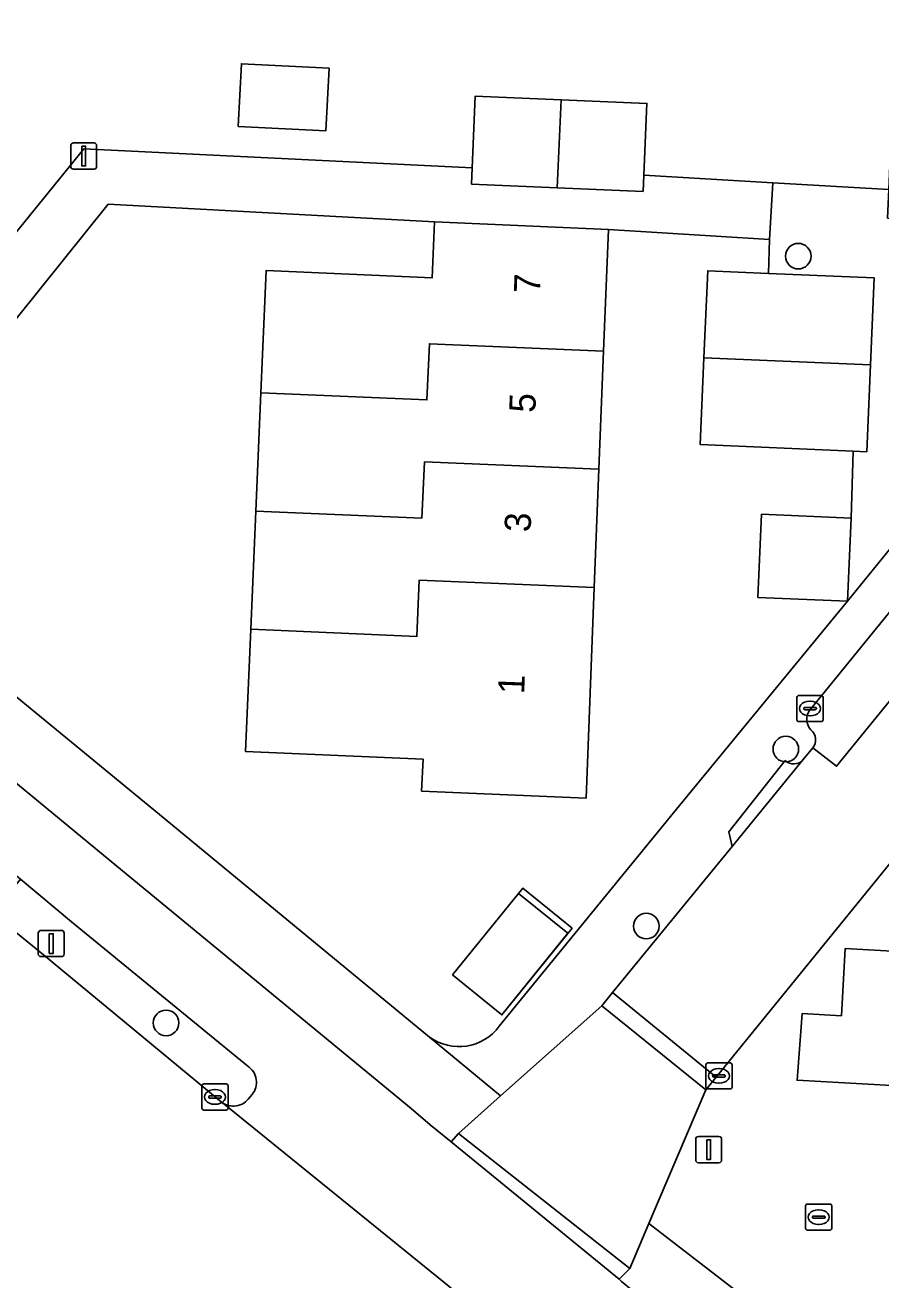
# Model space of a CAD drawing. Extents: x 162989 to 165008, y 383432 to 384338.
# Drawn here: x 164414.28 to 164447, y 383543.79 to 383591.76 of the extents above; entities that cross this region are included whole.
import ezdxf

# ---------------------------------------------------------------- set-up
doc = ezdxf.new("R2010")
doc.units = 0
for name, color, linetype in [('IMGEO_Boom', 7, 'Continuous'), ('IMGEO_Erf', 7, 'Continuous'), ('IMGEO_Fietspad_open', 7, 'Continuous'), ('IMGEO_Groenvoorziening', 7, 'Continuous'), ('IMGEO_Kolk', 7, 'Continuous'), ('IMGEO_Lichtmast', 7, 'Continuous'), ('IMGEO_Pand', 7, 'Continuous'), ('IMGEO_Pand_nummerreeks', 7, 'Continuous'), ('IMGEO_Pand_vergunning_verleend', 7, 'Continuous'), ('IMGEO_Parkeervlak_open', 7, 'Continuous'), ('IMGEO_Rijbaan_lokaal_open', 7, 'Continuous'), ('IMGEO_Voetpad_open', 7, 'Continuous')]:
    doc.layers.add(name, color=color, linetype=linetype)

msp = doc.modelspace()

# ---------------------------------------------------------------- linework, layer by layer
at = {"layer": 'IMGEO_Boom'}
for centre in [(164443.845, 383582.925), (164443.368, 383564.084), (164438.034, 383557.317), (164419.671, 383553.617)]:
    msp.add_circle(centre, 0.489, dxfattribs=at)
at = {"layer": 'IMGEO_Erf'}
for points in [[(164405.306, 383573.211), (164416.525, 383587.022), (164431.377, 383586.306), (164431.495, 383589.046), (164434.775, 383588.905), (164438.055, 383588.764), (164437.937, 383586.015), (164442.875, 383585.731), (164447.306, 383585.477), (164447.527, 383590.599), (164450.828, 383590.457), (164454.13, 383590.315), (164453.951, 383586.161), (164454.949, 383586.096), (164455.073, 383588.585), (164460.646, 383588.116), (164466.476, 383595.416), (164468.237, 383598.107)], [(164432.411, 383553.488), (164439.299, 383561.922), (164445.728, 383569.733), (164442.304, 383569.88), (164442.441, 383573.061), (164445.865, 383572.914), (164445.941, 383575.47), (164440.096, 383575.721), (164440.239, 383579.042), (164440.382, 383582.365), (164442.702, 383582.265), (164442.744, 383583.566), (164436.586, 383583.949), (164436.402, 383579.296), (164436.224, 383574.777), (164436.046, 383570.258), (164435.728, 383562.21), (164429.442, 383562.48), (164429.495, 383563.702), (164422.707, 383563.993), (164422.908, 383568.663), (164423.102, 383573.182), (164423.296, 383577.701), (164423.497, 383582.372), (164429.846, 383582.099), (164429.938, 383584.235), (164417.457, 383584.908), (164406.935, 383571.831), (164419.421, 383561.588), (164429.74, 383553.077)]]:
    msp.add_lwpolyline(points, dxfattribs=at)
for points in [[(164425.903, 383590.114), (164425.784, 383587.716), (164422.429, 383587.883), (164422.548, 383590.281)], [(164430.622, 383555.452), (164433.307, 383558.765), (164435.196, 383557.234), (164432.511, 383553.921)]]:
    msp.add_lwpolyline(points, close=True, dxfattribs=at)
msp.add_arc((164430.869, 383554.627), 1.918, 233.9466, 323.5489, dxfattribs=at)
at = {"layer": 'IMGEO_Fietspad_open'}
for points in [[(164320.149, 383636.549), (164338.569, 383621.368), (164355.855, 383607.134), (164360.495, 383603.371), (164385.072, 383583.018), (164402.919, 383568.352), (164414.101, 383559.114), (164416.06, 383557.479), (164422.791, 383551.963)], [(164438.67, 383542.429), (164437.09, 383543.73), (164436.992, 383543.815), (164430.566, 383549.073), (164429.773, 383549.72), (164429.037, 383550.342), (164417.789, 383559.607), (164405.287, 383569.915), (164386.954, 383585.032), (164362.228, 383605.446)], [(164421.813, 383550.569), (164441.129, 383534.933)], [(164422.959, 383550.88), (164422.815, 383550.707)]]:
    msp.add_lwpolyline(points, dxfattribs=at)
for centre, radius, start, end in [((164422.402, 383551.348), 0.727, 319.9447, 57.6907), ((164422.237, 383551.182), 0.745, 235.3669, 273.0368), ((164422.24, 383551.186), 0.748, 272.7924, 320.2526)]:
    msp.add_arc(centre, radius, start, end, dxfattribs=at)
at = {"layer": 'IMGEO_Groenvoorziening'}
for points in [[(164416.06, 383557.479), (164414.101, 383559.114), (164413.026, 383557.813), (164414.983, 383556.218), (164421.541, 383550.787), (164421.715, 383550.649), (164421.813, 383550.569)], [(164422.791, 383551.963), (164416.06, 383557.479)], [(164422.815, 383550.707), (164422.959, 383550.88)]]:
    msp.add_lwpolyline(points, dxfattribs=at)
for centre, radius, start, end in [((164422.402, 383551.348), 0.727, 319.9447, 57.6907), ((164422.237, 383551.182), 0.745, 235.3669, 273.0368), ((164422.24, 383551.186), 0.748, 272.7924, 320.2526)]:
    msp.add_arc(centre, radius, start, end, dxfattribs=at)
at = {"layer": 'IMGEO_Kolk'}
for p, q in [((164443.794, 383565.207), (164443.794, 383566.059)), ((164443.869, 383566.133), (164444.721, 383566.133)), ((164444.282, 383565.913), (164444.307, 383565.913)), ((164444.795, 383566.059), (164444.795, 383565.207)), ((164444.053, 383565.627), (164444.053, 383565.639)), ((164444.491, 383565.59), (164444.093, 383565.59)), ((164444.096, 383565.676), (164444.494, 383565.676)), ((164444.537, 383565.639), (164444.537, 383565.627)), ((164444.721, 383565.133), (164443.869, 383565.133)), ((164444.305, 383565.353), (164444.28, 383565.353)), ((164440.311, 383551.165), (164440.311, 383552.017)), ((164440.386, 383552.091), (164441.238, 383552.091)), ((164441.312, 383552.017), (164441.312, 383551.165)), ((164440.57, 383551.585), (164440.57, 383551.597)), ((164441.008, 383551.548), (164440.61, 383551.548)), ((164440.613, 383551.634), (164441.011, 383551.634)), ((164440.799, 383551.871), (164440.824, 383551.871)), ((164441.054, 383551.597), (164441.054, 383551.585)), ((164421.04, 383550.36), (164421.04, 383551.212)), ((164421.115, 383551.286), (164421.967, 383551.286)), ((164421.528, 383551.066), (164421.553, 383551.066)), ((164422.041, 383551.212), (164422.041, 383550.36)), ((164441.238, 383551.091), (164440.386, 383551.091)), ((164440.822, 383551.311), (164440.797, 383551.311)), ((164421.299, 383550.78), (164421.299, 383550.792)), ((164421.737, 383550.743), (164421.339, 383550.743)), ((164421.342, 383550.829), (164421.74, 383550.829)), ((164421.783, 383550.792), (164421.783, 383550.78)), ((164421.967, 383550.286), (164421.115, 383550.286)), ((164421.551, 383550.506), (164421.526, 383550.506)), ((164444.2, 383546.692), (164445.052, 383546.692)), ((164444.125, 383545.766), (164444.125, 383546.618)), ((164444.427, 383546.235), (164444.825, 383546.235)), ((164444.613, 383546.472), (164444.638, 383546.472)), ((164445.126, 383546.618), (164445.126, 383545.766)), ((164444.384, 383546.186), (164444.384, 383546.198)), ((164444.822, 383546.149), (164444.424, 383546.149)), ((164444.636, 383545.912), (164444.611, 383545.912)), ((164444.868, 383546.198), (164444.868, 383546.186)), ((164445.052, 383545.692), (164444.2, 383545.692))]:
    msp.add_line(p, q, dxfattribs=at)
for points in [[(164443.794, 383565.207), (164443.794, 383566.059)], [(164443.869, 383566.133), (164444.721, 383566.133)], [(164444.795, 383566.059), (164444.795, 383565.207)], [(164444.721, 383565.133), (164443.869, 383565.133)], [(164440.311, 383551.165), (164440.311, 383552.017)], [(164440.386, 383552.091), (164441.238, 383552.091)], [(164441.312, 383552.017), (164441.312, 383551.165)], [(164421.04, 383550.36), (164421.04, 383551.212)], [(164421.115, 383551.286), (164421.967, 383551.286)], [(164422.041, 383551.212), (164422.041, 383550.36)], [(164441.238, 383551.091), (164440.386, 383551.091)], [(164421.967, 383550.286), (164421.115, 383550.286)], [(164444.2, 383546.692), (164445.052, 383546.692)], [(164444.125, 383545.766), (164444.125, 383546.618)], [(164445.126, 383546.618), (164445.126, 383545.766)], [(164445.052, 383545.692), (164444.2, 383545.692)]]:
    msp.add_lwpolyline(points, dxfattribs=at)
for centre, radius, start, end in [((164443.871, 383566.057), 0.0765, 91.552, 178.448), ((164443.871, 383566.057), 0.0765, 91.552, 178.448), ((164444.719, 383566.057), 0.0765, 1.552, 88.448), ((164444.719, 383566.057), 0.0765, 1.552, 88.448), ((164444.093, 383565.636), 0.0403, 85.8775, 175.7526), ((164444.09, 383565.626), 0.0366, 178.938, 274.7102), ((164444.494, 383565.633), 0.043, 264.8664, 352.4533), ((164444.498, 383565.638), 0.0386, 1.7309, 96.639), ((164443.871, 383565.209), 0.0765, 181.552, 268.448), ((164443.871, 383565.209), 0.0765, 181.552, 268.448), ((164444.719, 383565.209), 0.0765, 271.552, 358.448), ((164444.719, 383565.209), 0.0765, 271.552, 358.448), ((164440.388, 383552.015), 0.0765, 91.552, 178.448), ((164440.388, 383552.015), 0.0765, 91.552, 178.448), ((164441.236, 383552.015), 0.0765, 1.552, 88.448), ((164441.236, 383552.015), 0.0765, 1.552, 88.448), ((164440.61, 383551.594), 0.0403, 85.8775, 175.7526), ((164440.607, 383551.584), 0.0366, 178.938, 274.7102), ((164441.011, 383551.591), 0.043, 264.8664, 352.4533), ((164441.015, 383551.596), 0.0386, 1.7309, 96.639), ((164421.117, 383551.21), 0.0765, 91.552, 178.448), ((164421.117, 383551.21), 0.0765, 91.552, 178.448), ((164421.965, 383551.21), 0.0765, 1.552, 88.448), ((164421.965, 383551.21), 0.0765, 1.552, 88.448), ((164440.388, 383551.167), 0.0765, 181.552, 268.448), ((164440.388, 383551.167), 0.0765, 181.552, 268.448), ((164441.236, 383551.167), 0.0765, 271.552, 358.448), ((164441.236, 383551.167), 0.0765, 271.552, 358.448), ((164421.339, 383550.789), 0.0403, 85.8775, 175.7526), ((164421.336, 383550.779), 0.0366, 178.938, 274.7102), ((164421.74, 383550.786), 0.043, 264.8664, 352.4533), ((164421.744, 383550.791), 0.0386, 1.7309, 96.639), ((164421.117, 383550.362), 0.0765, 181.552, 268.448), ((164421.117, 383550.362), 0.0765, 181.552, 268.448), ((164421.965, 383550.362), 0.0765, 271.552, 358.448), ((164421.965, 383550.362), 0.0765, 271.552, 358.448), ((164444.202, 383546.616), 0.0765, 91.552, 178.448), ((164444.202, 383546.616), 0.0765, 91.552, 178.448), ((164445.05, 383546.616), 0.0765, 1.552, 88.448), ((164445.05, 383546.616), 0.0765, 1.552, 88.448), ((164444.424, 383546.195), 0.0403, 85.8775, 175.7526), ((164444.829, 383546.197), 0.0386, 1.7309, 96.639), ((164444.202, 383545.768), 0.0765, 181.552, 268.448), ((164444.202, 383545.768), 0.0765, 181.552, 268.448), ((164444.421, 383546.185), 0.0366, 178.938, 274.7102), ((164444.825, 383546.192), 0.043, 264.8664, 352.4533), ((164445.05, 383545.768), 0.0765, 271.552, 358.448), ((164445.05, 383545.768), 0.0765, 271.552, 358.448)]:
    msp.add_arc(centre, radius, start, end, dxfattribs=at)
for centre, major_axis, ratio, start_param, end_param in [((164444.281, 383565.633), (-0.387, 0.002), 0.722429, 4.712389, 7.853982), ((164444.306, 383565.633), (-0.39, 0.002), 0.717154, 1.570796, 4.712389), ((164440.798, 383551.591), (-0.387, 0.002), 0.722429, 4.712389, 7.853982), ((164440.823, 383551.591), (-0.39, 0.002), 0.717154, 1.570796, 4.712389), ((164421.527, 383550.786), (-0.387, 0.002), 0.722429, 4.712389, 7.853982), ((164421.552, 383550.786), (-0.39, 0.002), 0.717154, 1.570796, 4.712389), ((164444.612, 383546.192), (-0.387, 0.002), 0.722429, 4.712389, 7.853982), ((164444.637, 383546.192), (-0.39, 0.002), 0.717154, 1.570796, 4.712389)]:
    msp.add_ellipse(centre, major_axis=major_axis, ratio=ratio, start_param=start_param, end_param=end_param, dxfattribs=at)
at = {"layer": 'IMGEO_Lichtmast'}
for p, q in [((164416.025, 383586.352), (164416.025, 383587.152)), ((164416.025, 383587.152), (164416.025, 383586.352)), ((164416.125, 383587.252), (164416.915, 383587.252)), ((164416.915, 383587.252), (164416.125, 383587.252)), ((164417.015, 383587.152), (164417.015, 383586.352)), ((164417.015, 383586.352), (164417.015, 383587.152)), ((164416.915, 383586.252), (164416.125, 383586.252)), ((164416.125, 383586.252), (164416.915, 383586.252)), ((164414.784, 383556.251), (164414.784, 383557.051)), ((164414.784, 383557.051), (164414.784, 383556.251)), ((164414.884, 383557.151), (164415.674, 383557.151)), ((164415.674, 383557.151), (164414.884, 383557.151)), ((164415.774, 383557.051), (164415.774, 383556.251)), ((164415.774, 383556.251), (164415.774, 383557.051)), ((164415.674, 383556.151), (164414.884, 383556.151)), ((164414.884, 383556.151), (164415.674, 383556.151)), ((164439.923, 383548.374), (164439.923, 383549.174)), ((164439.923, 383549.174), (164439.923, 383548.374)), ((164440.023, 383549.274), (164440.813, 383549.274)), ((164440.813, 383549.274), (164440.023, 383549.274)), ((164440.913, 383549.174), (164440.913, 383548.374)), ((164440.913, 383548.374), (164440.913, 383549.174)), ((164440.813, 383548.274), (164440.023, 383548.274)), ((164440.023, 383548.274), (164440.813, 383548.274))]:
    msp.add_line(p, q, dxfattribs=at)
for points in [[(164416.445, 383587.127), (164416.595, 383587.127), (164416.595, 383586.377), (164416.445, 383586.377), (164416.445, 383587.127)], [(164415.204, 383557.026), (164415.354, 383557.026), (164415.354, 383556.276), (164415.204, 383556.276), (164415.204, 383557.026)], [(164440.343, 383549.149), (164440.493, 383549.149), (164440.493, 383548.399), (164440.343, 383548.399), (164440.343, 383549.149)]]:
    msp.add_lwpolyline(points, dxfattribs=at)
for centre, start, end in [((164416.125, 383587.152), 90, 180), ((164416.125, 383587.152), 90, 180), ((164416.915, 383587.152), 0, 90), ((164416.915, 383587.152), 360, 90), ((164416.125, 383586.352), 180, 270), ((164416.125, 383586.352), 180, 270), ((164416.915, 383586.352), 270, 0), ((164416.915, 383586.352), 270, 0), ((164414.884, 383557.051), 90, 180), ((164414.884, 383557.051), 90, 180), ((164415.674, 383557.051), 0, 90), ((164415.674, 383557.051), 360, 90), ((164414.884, 383556.251), 180, 270), ((164414.884, 383556.251), 180, 270), ((164415.674, 383556.251), 270, 0), ((164415.674, 383556.251), 270, 0), ((164440.023, 383549.174), 90, 180), ((164440.023, 383549.174), 90, 180), ((164440.813, 383549.174), 0, 90), ((164440.813, 383549.174), 360, 90), ((164440.023, 383548.374), 180, 270), ((164440.023, 383548.374), 180, 270), ((164440.813, 383548.374), 270, 0), ((164440.813, 383548.374), 270, 0)]:
    msp.add_arc(centre, 0.1, start, end, dxfattribs=at)
at = {"layer": 'IMGEO_Pand'}
for points in [[(164425.903, 383590.114), (164422.548, 383590.281), (164422.429, 383587.883), (164425.784, 383587.716)], [(164434.63, 383585.539), (164434.775, 383588.905), (164431.495, 383589.046), (164431.377, 383586.306), (164431.35, 383585.68)], [(164434.63, 383585.539), (164437.91, 383585.398), (164437.937, 383586.015), (164438.055, 383588.764), (164434.775, 383588.905)], [(164436.402, 383579.296), (164436.586, 383583.949), (164429.938, 383584.235), (164429.846, 383582.099), (164423.497, 383582.372), (164423.296, 383577.701), (164429.647, 383577.431), (164429.738, 383579.579)], [(164440.239, 383579.042), (164446.607, 383578.77), (164446.75, 383582.091), (164442.702, 383582.265), (164440.382, 383582.365)], [(164436.402, 383579.296), (164429.738, 383579.579), (164429.647, 383577.431), (164423.296, 383577.701), (164423.102, 383573.182), (164429.455, 383572.912), (164429.546, 383575.06), (164436.224, 383574.777)], [(164440.239, 383579.042), (164440.096, 383575.721), (164445.941, 383575.47), (164446.464, 383575.448), (164446.607, 383578.77)], [(164423.102, 383573.182), (164422.908, 383568.663), (164429.263, 383568.393), (164429.354, 383570.541), (164436.046, 383570.258), (164436.224, 383574.777), (164429.546, 383575.06), (164429.455, 383572.912)], [(164445.865, 383572.914), (164442.441, 383573.061), (164442.304, 383569.88), (164445.728, 383569.733)], [(164436.046, 383570.258), (164429.354, 383570.541), (164429.263, 383568.393), (164422.908, 383568.663), (164422.707, 383563.993), (164429.495, 383563.702), (164429.442, 383562.48), (164435.728, 383562.21)], [(164430.622, 383555.452), (164432.511, 383553.921), (164435.196, 383557.234), (164433.307, 383558.765)]]:
    msp.add_lwpolyline(points, close=True, dxfattribs=at)
at = {"layer": 'IMGEO_Pand_vergunning_verleend'}
msp.add_lwpolyline([(164430.622, 383555.452), (164433.149, 383558.569), (164435.028, 383557.046), (164432.511, 383553.921)], close=True, dxfattribs=at)
at = {"layer": 'IMGEO_Parkeervlak_open'}
for points in [[(164450.906, 383573.705), (164444.27, 383565.56)], [(164444.399, 383564.125), (164445.307, 383563.429), (164453.234, 383573.158), (164452.318, 383573.909)]]:
    msp.add_lwpolyline(points, dxfattribs=at)
msp.add_lwpolyline([(164448.333, 383551.171), (164448.495, 383553.581), (164449.98, 383553.497), (164450.119, 383556.212), (164445.635, 383556.455), (164445.495, 383553.891), (164443.996, 383553.977), (164443.797, 383551.427)], close=True, dxfattribs=at)
for centre, radius, start, end in [((164444.754, 383565.228), 0.587, 145.5468, 223.8907), ((164443.999, 383564.437), 0.507, 322.0225, 49.1378)]:
    msp.add_arc(centre, radius, start, end, dxfattribs=at)
at = {"layer": 'IMGEO_Rijbaan_lokaal_open'}
for points in [[(164436.741, 383554.773), (164440.704, 383551.546), (164451.186, 383564.43), (164450.262, 383565.18), (164455.043, 383571.019), (164455.961, 383570.286), (164459.108, 383574.155), (164455.151, 383577.376), (164453.606, 383575.486), (164452.318, 383573.909), (164453.234, 383573.158), (164445.307, 383563.429), (164444.399, 383564.125), (164444.035, 383563.681), (164441.321, 383560.366)], [(164436.741, 383554.773), (164436.33, 383554.271), (164440.309, 383551.06), (164440.704, 383551.546)], [(164430.849, 383549.393), (164430.566, 383549.073), (164436.992, 383543.815), (164437.398, 383544.226)]]:
    msp.add_lwpolyline(points, close=True, dxfattribs=at)
msp.add_lwpolyline([(164441.129, 383534.933), (164421.813, 383550.569), (164421.715, 383550.649), (164421.541, 383550.787), (164414.983, 383556.218), (164413.026, 383557.813), (164404.954, 383564.476), (164401.849, 383567.056), (164389.87, 383576.898)], dxfattribs=at)
at = {"layer": 'IMGEO_Voetpad_open'}
for points in [[(164322.475, 383638.205), (164340.418, 383623.433), (164362.228, 383605.446), (164386.954, 383585.032), (164405.287, 383569.915), (164417.789, 383559.607), (164429.037, 383550.342), (164429.773, 383549.72), (164430.566, 383549.073), (164430.849, 383549.393), (164432.464, 383550.83), (164429.74, 383553.077), (164419.421, 383561.588), (164406.935, 383571.831), (164405.306, 383573.211), (164388.61, 383586.991), (164362.648, 383608.377), (164361.014, 383609.748), (164342.325, 383625.076)], [(164468.237, 383598.107), (164466.476, 383595.416), (164460.646, 383588.116), (164458.82, 383585.845), (164445.728, 383569.733), (164439.299, 383561.922), (164432.411, 383553.488)], [(164444.27, 383565.56), (164450.906, 383573.705)], [(164451.186, 383564.43), (164440.704, 383551.546), (164440.309, 383551.06), (164438.134, 383545.953), (164443.143, 383542.084), (164450.015, 383537.395), (164450.024, 383537.59), (164450.359, 383544.892), (164449.457, 383544.934), (164449.607, 383548.179)], [(164444.035, 383563.681), (164444.399, 383564.125)], [(164429.74, 383553.077), (164432.464, 383550.83), (164436.33, 383554.271), (164436.741, 383554.773), (164441.321, 383560.366), (164441.192, 383560.915), (164443.348, 383563.643)], [(164443.348, 383563.643), (164441.192, 383560.915), (164441.321, 383560.366), (164444.035, 383563.681)], [(164450.015, 383537.395), (164443.143, 383542.084), (164438.134, 383545.953), (164437.398, 383544.226), (164436.992, 383543.815), (164437.09, 383543.73), (164438.67, 383542.429)]]:
    msp.add_lwpolyline(points, dxfattribs=at)
for points in [[(164405.306, 383573.211), (164406.935, 383571.831), (164417.457, 383584.908), (164429.938, 383584.235), (164436.586, 383583.949), (164442.744, 383583.566), (164442.875, 383585.731), (164437.937, 383586.015), (164437.91, 383585.398), (164434.63, 383585.539), (164431.35, 383585.68), (164431.377, 383586.306), (164416.525, 383587.022)], [(164458.82, 383585.845), (164454.949, 383586.096), (164453.951, 383586.161), (164453.862, 383584.094), (164450.56, 383584.236), (164447.259, 383584.378), (164447.306, 383585.477), (164442.875, 383585.731), (164442.744, 383583.566), (164442.702, 383582.265), (164446.75, 383582.091), (164446.607, 383578.77), (164446.464, 383575.448), (164445.941, 383575.47), (164445.865, 383572.914), (164445.728, 383569.733)], [(164443.797, 383551.427), (164443.996, 383553.977), (164445.495, 383553.891), (164445.635, 383556.455), (164450.119, 383556.212), (164449.98, 383553.497), (164448.495, 383553.581), (164448.333, 383551.171)], [(164440.309, 383551.06), (164436.33, 383554.271), (164432.464, 383550.83), (164430.849, 383549.393), (164437.398, 383544.226), (164438.134, 383545.953)]]:
    msp.add_lwpolyline(points, close=True, dxfattribs=at)
for centre, radius, start, end in [((164444.754, 383565.228), 0.587, 145.5468, 223.8907), ((164443.999, 383564.437), 0.507, 322.0225, 49.1378), ((164443.673, 383563.993), 0.478, 227.1048, 319.2272), ((164443.673, 383563.993), 0.478, 227.1048, 319.2272), ((164430.869, 383554.627), 1.918, 233.9466, 323.5489)]:
    msp.add_arc(centre, radius, start, end, dxfattribs=at)

# ---------------------------------------------------------------- texts
at = {"layer": 'IMGEO_Pand_nummerreeks'}
for s, p in [('7', (164433.967, 383581.492)), ('5', (164433.787, 383576.928)), ('3', (164433.607, 383572.364)), ('1', (164433.362, 383566.172))]:
    msp.add_text(s, height=1, rotation=87.7398, dxfattribs=at).set_placement(p)

doc.saveas('drawing.dxf')
